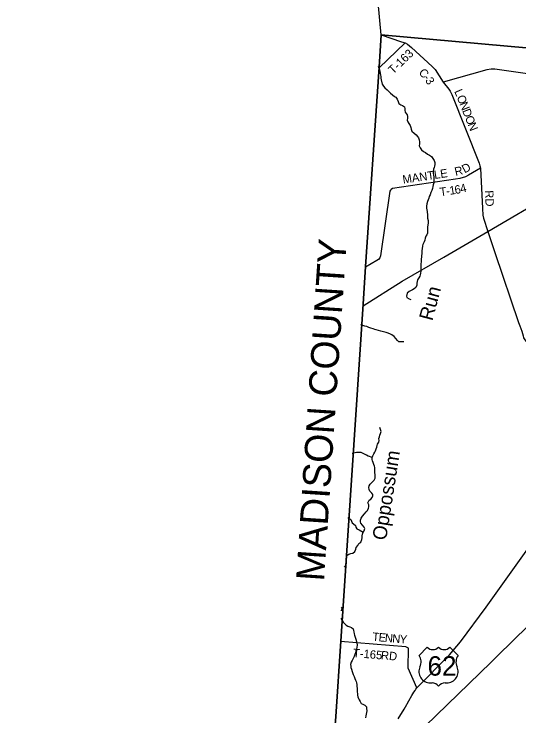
# Model space of a CAD drawing. Extents: x 1643459 to 2064572, y 425441 to 780708.
# Drawn here: x 1746483 to 1764524, y 636662 to 661772 of the extents above; entities that cross this region are included whole.
import ezdxf

# ---------------------------------------------------------------- set-up
doc = ezdxf.new("R2010")
doc.units = 0
for name, color, linetype in [('GM_X_Airport_Text_Class_2', 7, 'Continuous'), ('GM_X_City_Street', 7, 'Continuous'), ('GM_X_Interchange_Ramps', 7, 'Continuous'), ('GM_X_Interstate_Route', 7, 'Continuous'), ('GM_X_Major_River', 7, 'Continuous'), ('GM_X_Major_River_Text', 7, 'Continuous'), ('GM_X_Minor_Lake', 7, 'Continuous'), ('GM_X_Minor_River', 7, 'Continuous'), ('GM_X_Section_Text', 7, 'Continuous'), ('GM_X_Township_Road', 7, 'Continuous'), ('GM_X_Township_Subdivision', 7, 'Continuous'), ('GM_X_US_Route', 7, 'Continuous'), ('RD_X_Misc_Items', 7, 'Continuous'), ('RD_X_Wall', 7, 'Continuous'), ('SH_Named_Boundary', 7, 'Continuous')]:
    doc.layers.add(name, color=color, linetype=linetype)

msp = doc.modelspace()

# ---------------------------------------------------------------- linework, layer by layer
at = {"layer": 'GM_X_City_Street'}
msp.add_lwpolyline([(1757977, 636642), (1758154, 639332), (1758962, 651389), (1759045, 652740), (1759526, 659870), (1759596, 661027), (1771157, 659994)], dxfattribs=at)
at = {"layer": 'GM_X_Interstate_Route'}
msp.add_lwpolyline([(1792928, 659077), (1789408, 659196), (1786100, 659304), (1784956, 659328), (1781576, 659434), (1779741, 659492), (1773339, 659850), (1771560, 659962), (1771157, 659994), (1759596, 661027), (1759526, 659870), (1759045, 652740), (1758962, 651389), (1758154, 639332), (1757977, 636642), (1757708, 633208), (1757453, 629228), (1757203, 625316), (1757178, 624925), (1756763, 618445), (1756758, 618359), (1755763, 604727), (1755032, 592905)], dxfattribs=at)
at = {"layer": 'GM_X_Major_River_Text'}
for points in [[(1760463, 660745), (1759526, 659848)], [(1769489, 658563), (1769489, 658563), (1766964, 658781), (1766890, 658803), (1766834, 658835), (1765695, 659474), (1765601, 659500), (1765498, 659534), (1763659, 659795), (1763531, 659801), (1763377, 659777), (1761811, 659336)], [(1763151, 656257), (1762723, 656005), (1762617, 655949), (1762407, 655885), (1762261, 655859), (1760008, 655526), (1759958, 655498), (1759930, 655472), (1759912, 655440), (1759579, 653125), (1759557, 653049), (1759511, 652995), (1759451, 652959), (1759043, 652713)], [(1760878, 637668), (1760570, 638369), (1760580, 639085), (1760486, 639129), (1758153, 639328)]]:
    msp.add_lwpolyline(points, dxfattribs=at)
at = {"layer": 'GM_X_Minor_Lake'}
for points in [[(1759596, 661027), (1760333, 660783), (1760463, 660745), (1760543, 660696), (1760680, 660573), (1761421, 659891), (1761530, 659793), (1761811, 659336), (1762015, 659079), (1762061, 659007), (1762129, 658897), (1763107, 656439), (1763131, 656337), (1763151, 656257), (1763217, 654820)], [(1763217, 654820), (1763217, 654819), (1763228, 654579), (1763258, 654467), (1763411, 653996), (1763666, 653242)], [(1763666, 653242), (1763666, 653242), (1764511, 650743), (1764551, 650619), (1764623, 650429), (1764675, 650259), (1764685, 650191), (1764737, 650117), (1764841, 649991), (1766109, 648283), (1766219, 648135), (1766307, 648026), (1766450, 647928), (1768047, 647083)]]:
    msp.add_lwpolyline(points, dxfattribs=at)
at = {"layer": 'GM_X_Minor_River'}
msp.add_lwpolyline([(1742304, 619412), (1747296, 619048), (1751520, 618741), (1756758, 618359), (1756763, 618445), (1757178, 624925), (1757203, 625316), (1757453, 629228), (1757708, 633208), (1757977, 636642), (1758154, 639332), (1758962, 651389), (1759045, 652740), (1759526, 659870), (1759596, 661027), (1759497, 662188)], dxfattribs=at)
at = {"layer": 'GM_X_Township_Road'}
msp.add_lwpolyline([(1760023, 635174), (1763516, 638579), (1763759, 638818), (1764851, 639882)], dxfattribs=at)
at = {"layer": 'GM_X_US_Route'}
for points in [[(1759492, 659907), (1759517, 659841), (1759539, 659781), (1759553, 659731), (1759564, 659657), (1759574, 659588), (1759584, 659538), (1759592, 659474), (1759601, 659414), (1759641, 659266), (1759687, 659197), (1759738, 659129), (1759810, 659066), (1759880, 658996), (1759938, 658942), (1760001, 658879), (1760073, 658817), (1760125, 658793), (1760167, 658726), (1760203, 658642), (1760238, 658576), (1760300, 658519), (1760368, 658501), (1760432, 658449), (1760448, 658380), (1760451, 658330), (1760463, 658266), (1760527, 658166), (1760547, 658108), (1760540, 658043), (1760532, 657971), (1760554, 657913), (1760584, 657851), (1760637, 657785), (1760667, 657716), (1760675, 657658), (1760702, 657586), (1760780, 657514), (1760846, 657455), (1760900, 657393), (1760936, 657341), (1760961, 657276), (1760973, 657200), (1760967, 657130), (1760958, 657060), (1760990, 656988), (1761042, 656918), (1761118, 656849), (1761190, 656813), (1761261, 656764), (1761327, 656726), (1761397, 656670), (1761453, 656601), (1761499, 656529), (1761518, 656467), (1761520, 656385), (1761508, 656335), (1761489, 656281), (1761469, 656227), (1761461, 656145), (1761463, 656074), (1761474, 656004), (1761482, 655946), (1761486, 655874), (1761483, 655816), (1761477, 655736), (1761463, 655666), (1761444, 655602), (1761432, 655530), (1761410, 655464), (1761380, 655390), (1761349, 655310), (1761321, 655248), (1761303, 655188), (1761280, 655122), (1761260, 655066), (1761232, 654982), (1761219, 654896), (1761223, 654830), (1761235, 654770), (1761244, 654708), (1761252, 654580), (1761256, 654529), (1761259, 654467), (1761275, 654381), (1761279, 654299), (1761274, 654219), (1761262, 654161), (1761256, 654087), (1761253, 654021), (1761253, 653939), (1761227, 653877), (1761201, 653821), (1761178, 653757), (1761162, 653687), (1761138, 653621), (1761093, 653533), (1761079, 653475), (1761067, 653377), (1761060, 653317), (1761054, 653263)], [(1761054, 653263), (1761052, 653197), (1761047, 653129), (1761039, 653079), (1761031, 653019), (1761025, 652969), (1761026, 652907), (1761024, 652837), (1761022, 652785), (1761022, 652716), (1761019, 652644), (1761017, 652570), (1761011, 652500), (1761000, 652442), (1760984, 652390), (1760948, 652332), (1760898, 652265), (1760885, 652209), (1760881, 652144), (1760873, 652074), (1760838, 651994), (1760778, 651945), (1760716, 651903), (1760652, 651873), (1760599, 651843), (1760529, 651792), (1760511, 651682), (1760522, 651628), (1760606, 651583), (1760661, 651555)], [(1760408, 650048), (1760227, 650043), (1760180, 650098), (1760128, 650164), (1760060, 650232), (1759984, 650291), (1759930, 650323), (1759852, 650351), (1759782, 650374), (1759688, 650406), (1759590, 650433), (1759504, 650455), (1759428, 650473), (1759373, 650492), (1759321, 650506), (1759227, 650530), (1759161, 650557), (1759091, 650589), (1759017, 650612), (1758869, 650654)], [(1758285, 641980), (1758353, 642056), (1758364, 642140), (1758364, 642214), (1758356, 642286), (1758365, 642356), (1758391, 642414), (1758441, 642450), (1758521, 642475), (1758593, 642491), (1758656, 642549), (1758690, 642625), (1758712, 642693), (1758771, 642760), (1758799, 642830), (1758873, 642880), (1758910, 642974), (1758918, 643038), (1758918, 643102), (1758931, 643162), (1758959, 643234), (1758991, 643286), (1759014, 643364), (1758998, 643414), (1758932, 643492), (1758880, 643553), (1758860, 643605), (1758859, 643671), (1758883, 643739), (1758939, 643813), (1759008, 643892), (1759068, 643960), (1759112, 644014), (1759151, 644092), (1759165, 644146), (1759159, 644218), (1759130, 644290), (1759178, 644376), (1759228, 644422), (1759283, 644474), (1759309, 644538), (1759299, 644588), (1759269, 644638), (1759197, 644702), (1759172, 644763), (1759166, 644835), (1759176, 644893), (1759211, 644949), (1759271, 645016), (1759347, 645096), (1759384, 645168), (1759388, 645250), (1759386, 645304), (1759380, 645362), (1759377, 645422), (1759373, 645474), (1759369, 645548), (1759361, 645601), (1759340, 645661), (1759310, 645731), (1759296, 645787), (1759284, 645839), (1759285, 645909), (1759303, 645963), (1759343, 646037), (1759378, 646093), (1759400, 646147), (1759428, 646217), (1759444, 646279), (1759457, 646335), (1759469, 646389), (1759515, 646457), (1759526, 646513), (1759520, 646591), (1759546, 646653), (1759558, 646707), (1759575, 646771), (1759597, 646839), (1759581, 646909), (1759550, 646977)], [(1759285, 645909), (1759249, 645919), (1759189, 645944), (1759137, 645960), (1759077, 645992), (1759009, 646025), (1758957, 646057), (1758883, 646081), (1758825, 646082), (1758775, 646084), (1758725, 646082), (1758559, 646056)], [(1758405, 643761), (1758513, 643689), (1758540, 643636), (1758564, 643572), (1758616, 643540), (1758678, 643472), (1758692, 643419), (1758733, 643357), (1758815, 643321), (1758959, 643234)], [(1758180, 640422), (1758187, 640434), (1758212, 640475), (1758210, 640524), (1758189, 640558)], [(1758162, 640159), (1758242, 640020), (1758356, 639913), (1758410, 639875), (1758478, 639845), (1758544, 639822), (1758604, 639782), (1758616, 639722), (1758625, 639666), (1758637, 639600), (1758645, 639550), (1758669, 639475), (1758696, 639415), (1758716, 639331), (1758728, 639275), (1758739, 639199), (1758731, 639127), (1758715, 639053), (1758696, 638987), (1758682, 638921), (1758664, 638857), (1758638, 638787), (1758597, 638713), (1758559, 638649), (1758527, 638581), (1758510, 638505), (1758512, 638449), (1758522, 638393), (1758542, 638341), (1758564, 638255)], [(1758564, 638255), (1758599, 638147), (1758635, 638069), (1758661, 638003), (1758688, 637944), (1758704, 637894), (1758714, 637842), (1758733, 637783), (1758737, 637713), (1758740, 637661), (1758744, 637587), (1758747, 637524), (1758759, 637456), (1758761, 637404), (1758770, 637347), (1758794, 637285), (1758816, 637235), (1758855, 637182), (1758889, 637112), (1758941, 637082), (1759013, 637051), (1759076, 636984), (1759080, 636926), (1759083, 636842), (1759081, 636784), (1759067, 636732), (1759050, 636663), (1759038, 636593)]]:
    msp.add_lwpolyline(points, dxfattribs=at)
at = {"layer": 'RD_X_Misc_Items'}
msp.add_lwpolyline([(1758958, 651336), (1760356, 652210), (1761839, 653079), (1763411, 653996), (1767961, 656661), (1770832, 658339), (1771559, 658777), (1773339, 659850)], dxfattribs=at)
at = {"layer": 'RD_X_Wall'}
for points in [[(1760418, 636909), (1760516, 637072), (1760529, 637094), (1760592, 637202), (1760701, 637393), (1760773, 637514), (1760812, 637575), (1760841, 637619), (1760874, 637664), (1760878, 637668), (1762048, 638848), (1762441, 639310), (1763356, 640548), (1764960, 642812), (1767796, 646723), (1768047, 647083), (1771696, 652117), (1771938, 652418), (1773291, 653631), (1773292, 653631)], [(1760212, 636565), (1760418, 636909)]]:
    msp.add_lwpolyline(points, dxfattribs=at)
at = {"layer": 'SH_Named_Boundary'}
for p, q in [((1761245, 639119), (1760955, 638829)), ((1762347, 638829), (1762057, 639119)), ((1761361, 637843), (1761419, 637843)), ((1761883, 637843), (1761941, 637843))]:
    msp.add_line(p, q, dxfattribs=at)
for centre, radius, start, end in [((1761448, 639326), 290, 225.573, 314.427), ((1761854, 639326), 290, 225.573, 314.427), ((1760622, 638596), 406, 334.5471, 35.0009), ((1762680, 638596), 406, 144.9991, 205.4529), ((1761356, 638249), 406, 154.8319, 270.6383), ((1761945, 638249), 406, 269.3617, 25.1681), ((1761419, 637553), 290, 36.8699, 90), ((1761883, 637553), 290, 90, 143.1301)]:
    msp.add_arc(centre, radius, start, end, dxfattribs=at)

# ---------------------------------------------------------------- texts
at = {"layer": 'GM_X_Airport_Text_Class_2'}
for s in ['/', '0']:
    msp.add_text(s, height=1, dxfattribs=at).set_placement((1761650, 638446))
msp.add_text('62', height=1, rotation=0, dxfattribs=at).set_placement((1761444, 638239))
at = {"layer": 'GM_X_Interchange_Ramps'}
for s, height, rotation, p in [('Run', 500, 75.1148, (1761430, 650772)), ('Oppossum', 499.9, 81.1154, (1759776, 642926))]:
    msp.add_text(s, height=height, rotation=rotation, dxfattribs=at).set_placement(p)
at = {"layer": 'GM_X_Major_River'}
for s, rotation, p in [('T-163', 43.7502, (1760026, 659604)), ('D', 28.9229, (1762585, 656068)), ('MANTLE', 8.457, (1760388, 655703)), ('R', 12.9026, (1762261, 655981)), ('6', 8.9332, (1762247, 655332)), ('4', 14.5909, (1762461, 655368)), ('T', 8.0749, (1761715, 655256)), ('-', 8.102, (1761937, 655288)), ('1', 8.2237, (1762060, 655305)), ('T', 355.0483, (1759276, 639353)), ('E', 355.0483, (1759500, 639334)), ('N', 355.047, (1759723, 639314)), ('N', 355.0504, (1759986, 639292)), ('Y', 354.5714, (1760249, 639269)), ('T-165', 355.2124, (1758585, 638771)), ('RD', 355.0738, (1759583, 638692))]:
    msp.add_text(s, height=300, rotation=rotation, dxfattribs=at).set_placement(p)
at = {"layer": 'GM_X_Section_Text'}
for s, rotation, p in [('C', 315.2498, (1760920, 659651)), ('-', 308.4703, (1761089, 659485)), ('3', 302.7793, (1761161, 659395)), ('L', 293.7197, (1762205, 659007)), ('O', 291.7913, (1762294, 658804)), ('N', 291.7405, (1762392, 658559)), ('D', 291.7388, (1762490, 658314)), ('O', 291.739, (1762587, 658068)), ('N', 291.739, (1762685, 657823)), ('RD', 272.4677, (1763309, 655460))]:
    msp.add_text(s, height=300, rotation=rotation, dxfattribs=at).set_placement(p)
at = {"layer": 'GM_X_Township_Subdivision'}
msp.add_text('MADISON COUNTY', height=1000, rotation=86.1829, dxfattribs=at).set_placement((1757557, 641461))
at = {"layer": 'SH_Named_Boundary'}
msp.add_text('62', height=696.1, dxfattribs=at).set_placement((1761257, 638104))

doc.saveas('drawing.dxf')
